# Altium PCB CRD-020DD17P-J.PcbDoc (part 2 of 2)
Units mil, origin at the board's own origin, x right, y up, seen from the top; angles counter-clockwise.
Board outline 2331 x 1574.8 mil, 4 copper layers (TOP, GND02, PWR03, BOTTOM), stack 63 mil thick; 83 components, 45 nets, 202 pads, 150 vias.
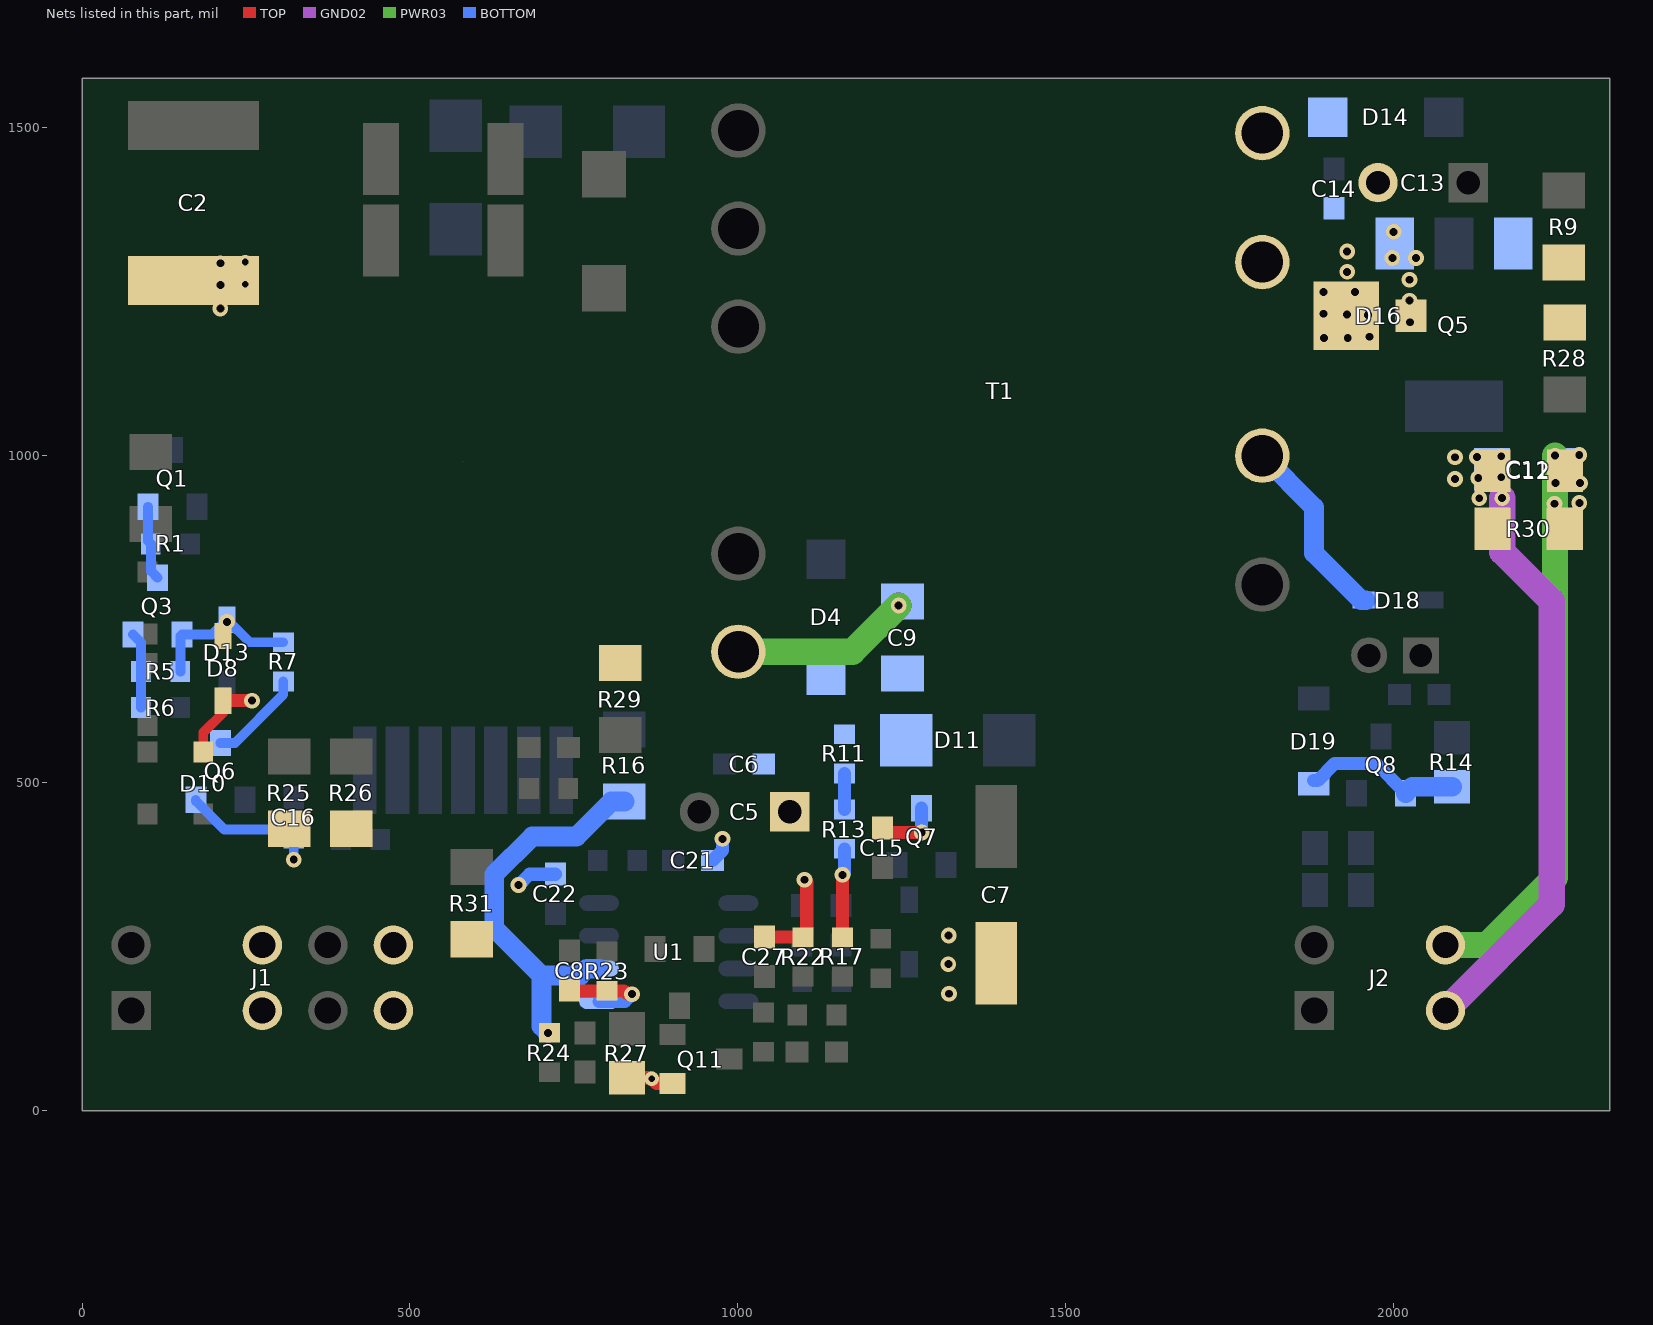
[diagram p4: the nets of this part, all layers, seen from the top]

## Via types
v1: diameter 24, hole 12, TOP to BOTTOM, 134 vias
v2: diameter 22, hole 10, TOP to BOTTOM, 16 vias

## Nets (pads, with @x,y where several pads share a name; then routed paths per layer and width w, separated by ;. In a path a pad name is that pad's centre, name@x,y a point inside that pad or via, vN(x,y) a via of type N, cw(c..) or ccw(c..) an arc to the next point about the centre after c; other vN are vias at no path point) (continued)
NETD8_2: D8.2 D13.1 Q3.B R5.2 R7.2 | length 260.1
  TOP w15: D8.2@215,724.02 215,739.8 v1(221,745.8)
  BOTTOM w15: R5.2@150,669.8 150,724.09 Q3.B@152.4,726.49 198.48,726.49 D13.1@221,749.02 255.21,714.8 R7.2@307,714.8
NETD14_1: D14.1 T1.14
NETD16_2: D16.2 Q5.1 R9.1 R28.1
  other v1: 2026,1202.8 2025,1235.8 2025,1267.8 1999,1300.8 2035,1300.8 2001,1340.8
NETD18_1: D18.1 T1.10 | length 290
  BOTTOM w30: T1.10@1800.61,999.38 1879.55,920.43 1879.55,850.62 1951.35,778.82 D18.1@1958.35,778.82
NETD19_2: D19.2 Q8.B R14.1 | length 244.5
  BOTTOM w20: D19.2@1879.15,503.7 1884.9,503.7 1911,529.8 1974.08,529.8 Q8.B@2019.39,484.49
  BOTTOM w30: Q8.B@2019.39,484.49 2029.2,494.3 R14.1@2090,494.3
NETQ1_E: Q1.E Q3.C R1.1 | length 114.3
  BOTTOM w15: Q1.E@100.6,921.49 100.6,869.21 R1.1@105,864.8 105,823.11 Q3.C@115,813.11
NETQ3_E: Q3.E R5.1 R6.2 | length 116.8
  BOTTOM w15: Q3.E@77.6,726.49 90,714.09 R5.1@90,669.8 R6.2@90,614.8
NETQ6_3: Q6.3 R7.1 | length 146.5
  BOTTOM w15: Q6.3@210.99,561.11 233.31,561.11 307,634.8 R7.1@307,654.8
NETR11_2: R11.2 R13.2 | length 55
  BOTTOM w20: R13.2@1163.08,459.43 R11.2@1163.08,514.43
NETR13_1: R13.1 R17.1 | length 135.9
  TOP w20: R17.1@1160,264.8 v1(1160,359.83)
  BOTTOM w20: v1(1160,359.83) 1163.08,362.91 R13.1@1163.08,399.43
NETR16_1: R16.1 R24.2 U1.6 | length 614.6
  TOP w20: v1(711.12,118.74) R24.2@713.12,118.74
  BOTTOM w30: v1(711.12,118.74) 700.95,128.91 700.95,206.36 ; U1.6@788.7,216.8 770.39,216.8 759.95,206.36 700.95,206.36 ; R16.1@827.49,471.7 807.49,471.7 754.24,418.45 686.95,418.45 628.71,360.21 628.71,278.6 700.95,206.36
P_15V: C5.1 C6.1 C9.1 D4.2 D11.1 J1.9 J1.10 R11.1 R31.2
PGND: C2.2 C7.2 C8.2 C9.2 C15.2 C16.1 C21.1 C22.1 C27.1 D8.1 D10.1 J1.5 J1.6 Q6.2 Q7.3 Q11.2 R22.1 R23.2 R25.2 R26.2 R27.2 R29.2 T1.6 U1.5 | length 1204.2
  TOP w15: D10.1@185,547.05 185,576.8 215,606.8 D8.1@215,625.59
  TOP w20: D8.1@215,625.59 v1(259.21,625.59) ; C8.2@744,183.8 745,182.8 R23.2@801,182.8 827,182.8 832,177.8 v1(839,177.8) ; R27.2@831.07,50.32 867.63,50.32 v2(869.03,48.92) 876.55,41.41 Q11.2@900.76,41.41 ; C27.1@1041,264.8 R22.1@1100,264.8 1105.55,270.35 1105.55,348.84 v1(1102.1,352.29) ; C15.2@1220.96,431.3 1227.77,424.49 v1(1280.97,424.49)
  PWR03 w40: T1.6@1001.39,700.17 1175.21,700.17 v1(1245.8,770.75)
  BOTTOM w5: v1(1245.8,770.75) C9.2@1251.74,776.69
  BOTTOM w15: Q6.2@173.58,474.49 173.58,472.22 217,428.8 312,428.8 C16.1@323,417.8 v1(323,383.02)
  BOTTOM w20: v1(666.02,344.19) 682.63,360.8 C22.1@722,360.8 ; U1.5@788.7,166.8 828,166.8 v1(839,177.8) ; C21.1@962,381.8 977.02,396.82 v1(977.02,414.8) ; v1(1280.97,424.49) Q7.3@1280.97,461.58
  other v1: 1322.52,178.44 1321.66,223.59 1322.09,267.45 211,1223.8 211,1259.8 211,1292.8
  other v2: 249,1260.8 249,1294.8
S_15V: C11.1 C12.1 J2.6 Q5.3 R30.2 | length 853.1
  PWR03 w40: J2.6@2080,252.8 2143.76,252.8 2247.12,356.16 v1(2247.12,999.36)
  other v1: 2246.28,925.97 2284.28,926.97 2248.12,957.36 2285.12,957.36 2284.12,1000.36
SGND: C11.2 C12.2 C13.2 C14.2 D16.1 J2.5 R30.1 T1.12 | length 880.3
  GND02 w40: J2.5@2080,152.8 2242.27,315.07 2242.27,777.14 2166.52,852.89 v1(2166.52,934.53)
  other v1: 2131.54,934.36 2094.55,963.82 2130.12,965.36 2165.12,966.36 2094.55,996.82 2128.12,997.36 2165.12,998.36 1895,1178.8 1931,1178.8 1964,1180.8 1962,1213.8 1930,1214.8 1894,1215.8 1894,1248.8 1942,1248.8 1930,1279.8 1930,1310.8
pads on no net: T1.2

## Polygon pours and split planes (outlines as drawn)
NETD4_1 on BOTTOM "BOTTOM-NETD4_1" (solid, remove dead copper, pour order 8): 976,889.8 1088,889.8 1106,871.8 1151,871.8 1161.64,871.8 1165.31,868.13 1165.31,858.11 1165,857.8 1165,817.8 1165,810.84 1161.27,807.11 1154.31,807.11 1154,806.8 988,806.8 972.49,806.8 959,820.29 959,835.8 959,872.8
P_15V on BOTTOM "BOTTOM-P_15V" (solid, remove dead copper, pour order 27): 1110,695.8 1102,687.8 1102,686.8 1092.47,677.27 1092.47,621.47 1040.88,569.88 1029.12,558.12 1029.12,429.39 1038.87,419.64 1050.96,419.64 1101.72,419.64 1117.85,435.77 1117.85,537.42 1136.68,556.25 1200.21,556.25 1209.28,547.18 1209.28,529.55 1218.02,520.81 1296.33,520.81 1300.03,524.51 1300.03,570.39 1300.03,683.16 1285.83,697.36 1111.56,697.36
NETC13_1 on BOTTOM "BOTTOM-NETC13_1" (solid, remove dead copper, pour order 25): 2121,1528.8 2146,1503.8 2146,1390.8 2123,1367.8 2123,1361.8 2123,1159.8 2168,1114.8 2168,1039.8 2164,1035.8 2023,1035.8 2018,1040.8 2018,1109.8 2064,1155.8 2064,1282.8 2064,1362.8 2080,1378.8 2080,1433.8 2046,1467.8 2046,1521.8 2046,1544.8 2048,1546.8 2103,1546.8
NETC1_1 on BOTTOM "BOTTOM-NETC1_1" (solid, remove dead copper, pour order 17): 818,1452.8 906,1452.8 971,1452.8 1002,1452.8 1022,1452.8 1043,1473.8 1043,1516.8 1008,1551.8 820,1551.8 810,1541.8 810,1460.8
NETC7_1 on BOTTOM "BOTTOM-NETC7_1" (solid, remove dead copper, pour order 16): 1388.71,369.92 1452.85,369.92 1463.91,380.98 1463.91,600.71 1455.06,609.56 1375.34,609.56 1371.96,606.18 1371.96,514.51 1371.96,386.67
SGND on BOTTOM "BOTTOM-SGND" (solid, remove dead copper, pour order 2): 2108.96,1015.1 2174.96,1015.1 2181.96,1008.1 2181.96,941.1 2181.96,924.1 2177.96,920.1 2100.44,920.1 2082.1,938.44 2082.1,1005.64 2091.56,1015.1
NETD14_1 on BOTTOM "BOTTOM-NETD14_1" (solid, remove dead copper, pour order 5): 1931,1526.8 1931,1487.8 1927,1483.8 1847,1483.8 1831,1467.8 1815,1451.8 1784,1451.8 1761,1474.8 1761,1515.8 1779,1533.8 1792,1546.8 1922,1546.8 1931,1537.8
NETD16_2 on BOTTOM "BOTTOM-NETD16_2" (solid, remove dead copper, pour order 4): 1974,1363.8 1974,1296.8 2004,1266.8 2004,1210.8 2004,1200.8 2010,1194.8 2016,1188.8 2044,1188.8 2050,1194.8 2056,1200.8 2056,1338.8 2034,1360.8 2031,1363.8
NETD2_2 on BOTTOM "BOTTOM-NETD2_2" (solid, remove dead copper, pour order 7): 606,1385.8 457,1385.8 441,1369.8 441,1317.8 456,1302.8 599,1302.8 610,1313.8 610,1381.8
S_15V on BOTTOM "BOTTOM-S_15V" (solid, remove dead copper, pour order 18): 2184,1048.31 2184,1270.8 2172,1282.8 2159,1282.8 2153,1288.8 2153,1351.8 2165,1363.8 2207,1363.8 2213,1363.8 2224,1352.8 2224,1104.63 2297.09,1031.54 2297.09,949.41 2290.64,942.96 2235.17,942.96 2226.14,951.99 2226.14,1006.17
NETD6_1 on BOTTOM "BOTTOM-NETD6_1" (solid, remove dead copper, pour order 30): 735,1129.8 425,1129.8 375,1129.8 370,1124.8 370,864.8 375,859.8 420,859.8 430,859.8 485,859.8 785,859.8 787.5,862.3 790,862.3 790,944.8 790,1054.8 794.5,1059.3 889,1153.8 999,1153.8 1028,1153.8 1042,1167.8 1042,1221.8 1024,1239.8 995,1239.8 952,1239.8 875,1239.8 765,1129.8
NETC24_1 on BOTTOM "BOTTOM-NETC24_1" (solid, remove dead copper, pour order 26): 645,449.8 415,449.8 410,454.8 410,470.8 410,502.8 394,518.8 289,518.8 283,524.8 283,586.8 291,594.8 420,594.8 643,594.8 649,588.8 649,453.8
NETD1_2 on BOTTOM "BOTTOM-NETD1_2" (solid, remove dead copper, pour order 10): 537,1544.8 721,1544.8 731,1534.8 731,1454.8 728,1451.8 626,1451.8 615,1462.8 535,1462.8 530,1467.8 530,1537.8
SGND on BOTTOM "BOTTOM-SGND 1" (solid, remove dead copper, pour order 21): 1775,1254.8 1761,1268.8 1761,1274.8 1761,1281.8 1761,1314.8 1782,1335.8 1840,1393.8 1936,1393.8 1938,1393.8 1947,1402.8 1947,1425.8 1966,1444.8 1995,1444.8 2008.5,1431.3 2008.5,1411.3 2008.5,1398.8 1997,1387.3 1968.5,1387.3 1956,1374.8 1956,1284.8 1956,1262.8 1978,1240.8 1978,1168.8 1970,1160.8 1885,1160.8 1872,1173.8 1872,1257.8 1905,1290.8 1905,1334.8 1900,1339.8 1887,1339.8 1886,1338.8 1879,1338.8 1845,1304.8 1845,1269.8 1830,1254.8
NETC1_1 on TOP "TOP-NETC1_1" (solid, remove dead copper, pour order 13): 60,1481.8 60,1537.8 77,1554.8 268,1554.8 281,1541.8 281,1474.8 272,1465.8 76,1465.8
PGND on TOP "TOP-PGND" (solid, remove dead copper, pour order 20): 280,364.8 280.5,364.3 245,328.8 245,129.8 258,116.8 287,116.8 310,139.8 310,257.8 311.01,258.81 311.01,304.51 351.18,344.68 394.54,388.04 435.87,388.04 442.81,394.98 442.81,457.78 440.62,459.97 284.96,459.97 282.61,457.62 282.61,367.41
NETC13_1 on TOP "TOP-NETC13_1" (solid, remove dead copper, pour order 9): 2289.61,1375.39 2091.31,1375.39 2081.9,1384.8 2081.9,1445.31 2086.6,1450.01 2282.89,1450.01 2294.32,1438.58 2294.32,1380.1
AGND on TOP "TOP-AGND" (solid, remove dead copper, pour order 29): 343.27,136.96 343.27,266.02 343.27,309 406.38,372.11 482.3,372.11 486.38,376.19 536.21,426.02 639.17,426.02 675.13,461.98 682.92,461.98 763.08,461.98 778.88,477.78 778.88,592.06 792.32,605.5 958.36,605.5 974.76,589.1 974.76,439.05 932.82,397.11 697.54,397.11 636.12,335.7 636.04,335.61 549.83,335.61 518.06,303.84 455.12,303.84 424.11,272.83 424.11,268.38 424.11,135.95 410.67,122.51 357.72,122.51
NETD2_2 on TOP "TOP-NETD2_2" (solid, remove dead copper, pour order 6): 436,1507.8 477,1507.8 483,1501.8 483,1280.8 475,1272.8 432,1272.8 428,1276.8 428,1499.8
NETC24_1 on TOP "TOP-NETC24_1" (solid, remove dead copper, pour order 23): 480.65,450.8 638,450.8 648,460.8 648,585.8 644,589.8 455,589.8 285,589.8 270,574.8 270,520.81 280.42,510.39 440.58,510.39 449.99,500.98 449.99,481.46
S_15V on TOP "TOP-S_15V" (solid, remove dead copper, pour order 3): 2231.95,1011.67 2287.95,1011.67 2294.95,1004.67 2294.95,910.67 2294.95,872.51 2294.95,857.41 2289.78,852.24 2234.96,852.24 2232.64,854.57 2232.64,865.39 2232.64,905.99 2231.95,906.67
NETC13_1 on TOP "TOP-NETC13_1 1" (solid, remove dead copper, pour order 15): 2161,1035.8 2075,1035.8 2059,1051.8 2059,1114.8 2064,1119.8 2065.83,1121.63 2295.66,1121.63 2298.69,1118.6 2298.69,1047.01 2287.3,1035.62 2170.82,1035.62 2161.18,1035.62
PGND on TOP "TOP-PGND 1" (solid, remove dead copper, pour order 11): 1047,718.8 1023,742.8 983,742.8 982,741.8 974,741.8 953,720.8 844,720.8 792.5,720.8 785.77,714.07 785.77,655.92 790.14,651.55 852.99,651.55 860.24,658.8 963,658.8 963.5,659.31 974,648.8 1022,648.8 1047,673.8
P_15V on TOP "TOP-P_15V" (solid, remove dead copper, pour order 28): 461.7,120.76 444.28,138.17 444.28,269.97 461.76,287.45 621.99,287.45 712.83,378.29 954.33,378.29 1038.36,462.32 1038.36,475.93 1053.9,491.47 1108.02,491.47 1117.43,482.06 1117.43,430.98 988.69,302.24 755.77,302.24 744.34,290.81 742.65,290.81 707.7,255.86 647.32,195.48 571.08,195.48 530.26,154.66 496.36,120.76
NETD16_2 on TOP "TOP-NETD16_2" (solid, remove dead copper, pour order 22): 2125.5,1241.3 2144,1259.8 2145,1259.8 2205,1319.8 2285,1319.8 2295,1309.8 2295,1189.8 2285,1179.8 2020.5,1179.8 2016,1179.8 2010,1185.8 2009,1185.8 2005.5,1189.3 2005.5,1271.3 1974,1302.8 1974,1359.8 1978,1363.8 2024,1363.8 2028,1363.8 2035.5,1356.31 2057,1334.8 2057,1263.8 2079.5,1241.3
NETD6_2 on TOP "TOP-NETD6_2" (solid, remove dead copper, pour order 19): 685,1509.8 620,1509.8 620,1269.8 670,1269.8 670,1369.8 670,1389.8 674,1393.8 821,1393.8 830,1402.8 830,1484.8 805,1509.8
NETD6_1 on TOP "TOP-NETD6_1" (solid, remove dead copper, pour order 32): 735,1129.8 425,1129.8 375,1129.8 370,1124.8 370,864.8 375,859.8 420,859.8 430,859.8 485,859.8 785,859.8 785,939.8 785,1058.8 881,1154.8 1010,1154.8 1041,1185.8 1041,1212.8 1018,1235.8 999,1235.8 884,1235.8 880,1239.8 865,1254.8 830,1289.8 767,1289.8 763,1285.8 763,1157.8 745,1139.8
PGND on TOP "TOP-PGND 2" (solid, remove dead copper, pour order 12): 66,1217.8 60,1223.8 60,1297.8 67,1304.8 270,1304.8 273,1301.8 273,1234.8 267,1228.8 232,1228.8 215,1211.8 72,1211.8
PGND on TOP "TOP-PGND 3" (solid, remove dead copper, pour order 14): 1430.02,290.24 1430.02,159.52 1418.84,148.34 1305.32,148.34 1287.26,166.4 1287.26,278.2 1301.88,292.82 1427.44,292.82
SGND on TOP "TOP-SGND" (solid, remove dead copper, pour order 24): 1960,1268.8 1963,1265.8 1970,1265.8 1978,1257.8 1978,1181.8 2045,1114.8 2045,1043.8 2045,1025.42 2053.49,1016.93 2101.47,1016.93 2174.1,1016.93 2179.7,1011.33 2179.7,921.89 2179.7,857.4 2175.4,853.1 2125.31,853.1 2105.96,872.45 2105.96,922.75 2075.43,953.28 2029.85,953.28 1995,988.13 1995,999.8 1995,1104.8 1938,1161.8 1882,1161.8 1877,1166.8 1877,1263.8 1877,1287.8 1916,1326.8 1945,1326.8 1956,1315.8 1956,1272.8
NETD6_1 on GND02 "GND02-NETD6_1" (solid, remove dead copper, pour order 31): 846,1236.8 739,1129.8 375,1129.8 375,864.8 379,860.8 789,860.8 791,862.8 791,944.8 792.5,946.3 792.5,1058.3 888,1153.8 894.5,1160.3 1030.5,1160.3 1045,1174.8 1045,1216.8 1025,1236.8
NETC1_1 on GND02 "GND02-NETC1_1" (solid, remove dead copper, pour order 34): 116,124.8 110,124.8 55,124.8 45,134.8 45,1497.8 92,1544.8 150,1544.8 215,1544.8 930,1544.8 1031,1544.8 1052,1523.8 1052,1482.8 1025,1455.8 824,1455.8 800,1479.8 465,1479.8 245,1479.8 180,1479.8 150,1449.8 150,1384.8 150,1094.8 150,1004.8 150,427.8 139,416.8 139,260.8 139,147.8
SGND on GND02 "GND02-SGND" (solid, remove dead copper, pour order 1): 2085.4,1012.53 2174.4,1012.53 2181.4,1005.53 2181.4,928.53 2175.4,922.53 2113.4,922.53 2080.4,955.53 2080.4,1007.53
NETD6_1 on PWR03 "PWR03-NETD6_1" (solid, remove dead copper, pour order 33): 881,1240.8 774,1133.8 374,1133.8 362,1121.8 362,876.8 378,860.8 784,860.8 791,867.8 791,944.8 791,988.8 791,1020.8 861,1090.8 918,1147.8 1036,1147.8 1050,1161.8 1050,1225.8 1026,1249.8 890,1249.8
S_15V on PWR03 "PWR03-S_15V" (solid, remove dead copper, pour order 0): 2240.52,906.68 2234.52,912.68 2234.52,1011.68 2237.52,1014.68 2290.52,1014.68 2298.52,1006.68 2298.52,914.68 2290.52,906.68
PGND on PWR03 "PWR03-PGND" (solid, remove dead copper, pour order 35): 302,734.8 302,511.8 346.5,467.3 346.5,319.3 347,318.8 347,303.8 319,275.8 319,147.8 358,108.8 416,108.8 427,108.8 429,110.8 505,110.8 569,174.8 569,299.8 568.5,300.3 568.5,343.3 659,433.8 659,594.8 701,636.8 879,636.8 977,734.8 1030,734.8 1040,724.8 1040,650.8 1056,634.8 1466.58,634.8 1498.58,602.8 1498.58,193.85 1326.53,21.8 586,21.8 308,21.8 253,76.8 232,97.8 232,146.8 232,367.8 66,533.8 66,1295.8 77,1306.8 268,1306.8 300,1274.8 300,734.8

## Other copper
TOP:
  text "TOP" at 910,-190 h60
GND02:
  text "GND02" at 910,-190 h60
PWR03:
  text "PWR03" at 910,-190 h60
BOTTOM:
  text "BOTTOM" at 910,-190 h60

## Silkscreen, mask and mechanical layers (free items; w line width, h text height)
Top Overlay:
  drawing of 6236 lines, arcs and shapes, not listed
  text "CRD-020DD17P-J rev 1.0" at 72.24,1150.23 h35
  text "Silkscreen TOP" at 910,-190 h60
Bottom Overlay:
  text "Silkscreen BOTTOM" at 910,-190 h60
  text "SILKSCREEN BOTTOM" at 9573,-250 h100
Top Paste:
  text "Paste TOP" at 910,-190 h60
Bottom Paste:
  text "Paste BOTTOM" at 910,-190 h60
Top Solder:
  region: 375,1129.8 775,1129.8 785,1119.8 785,859.8 375,859.8 370,864.8 370,1124.8
  text "Soldermask TOP" at 910,-190 h60
  text "SOLDERMASK TOP" at 8333,-250 h100
Bottom Solder:
  region: 375,1129.8 778,1129.8 788,1119.8 788,862.8 785,859.8 375,859.8 370,864.8 370,1124.8
  text "Soldermask BOTTOM" at 910,-190 h60
  text "SOLDERMASK BOTTOM" at 9573,-250 h100
DESIGN_OUTLINE:
  lines w1: 0,0 2331,0 2331,1574.8 0,1574.8 0,0
DIMENSION:
  drawing of 890 lines, arcs and shapes, not listed
  text "40" at -1513.5,733.3 h125
  text "40" at -1513.5,733.3 h125
  text "1574.80" at -1046.5,733.3 h125
  text "1574.80" at -1046.5,733.3 h125
  text "59.21" at 324.5,-377.7 h125
  text "59.21" at 324.5,-377.7 h125
  text "2331.00" at 1163.5,-377.7 h125
  text "2331.00" at 1163.5,-377.7 h125
Title Block:
  lines w7.9: -11414.06,-7979.09 12601.64,-7979.09 ; -11414.06,-7979.09 12601.64,-7979.09 ; -11414.06,-7979.09 -11414.06,9343.71 ; -11414.06,-7979.09 -11414.06,9343.71 ; -11414.06,9343.71 12601.64,9343.71 ; -11414.06,9343.71 12601.64,9343.71 ; 12601.64,-7979.09 12601.64,9343.71 ; 12601.64,-7979.09 12601.64,9343.71
  lines w8: -10626.67,-7191.68 -10626.67,8556.32 ; -10626.67,-7191.68 -10626.67,8556.32 ; -10626.67,-7191.68 11814.24,-7191.68 ; -10626.67,-7191.68 11814.24,-7191.68 ; -10626.67,8556.32 11814.24,8556.32 ; -10626.67,8556.32 11814.24,8556.32 ; 7411.83,8006.32 11811.83,8006.32 7411.83,8006.32 ; 7411.83,8006.32 7411.83,8056.32 ; 7411.83,8006.32 7411.83,8056.32 ; 7411.83,8056.32 7411.83,8556.32 7411.83,8056.32 ; 7861.83,8156.32 7861.83,8306.32 7861.83,8156.32 ; 7861.83,8156.32 7861.83,8006.32 7861.83,8156.32 ; 9911.83,8156.32 9911.83,8306.32 9911.83,8156.32 ; 9911.83,8156.32 9911.83,8006.32 9911.83,8156.32 ; 10461.83,8156.32 10461.83,8306.32 10461.83,8156.32 ; 10461.83,8156.32 10461.83,8006.32 10461.83,8156.32 ; 11036.83,8156.32 11036.83,8306.32 11036.83,8156.32 ; 11036.83,8156.32 11036.83,8006.32 11036.83,8156.32 ; 11814.24,-7191.68 11814.24,8556.32 ; 11814.24,-7191.68 11814.24,8556.32 ; -11413.76,-5156.29 -10628.06,-5156.29 -11413.76,-5156.29 ; -11413.76,-1156.29 -10628.06,-1156.29 -11413.76,-1156.29 ; -11413.76,2843.71 -10628.06,2843.71 -11413.76,2843.71 ; -11413.76,6843.71 -10628.06,6843.71 -11413.76,6843.71 ; -11412.67,9341.51 -10626.06,8554.82 -11412.67,9341.51 ; -11412.46,-7977.09 -10625.67,-7190.29 -11412.46,-7977.09 ; -7414.06,-7978.79 -7414.06,-7193.39 -7414.06,-7978.79 ; -7414.06,8556.71 -7414.06,9342.01 -7414.06,8556.71 ; -3414.06,-7978.79 -3414.06,-7193.39 -3414.06,-7978.79 ; -3414.06,8556.71 -3414.06,9342.01 -3414.06,8556.71 ; 585.94,-7978.79 585.94,-7193.39 585.94,-7978.79 ; 585.94,8556.71 585.94,9342.01 585.94,8556.71 ; 4585.94,-7978.79 4585.94,-7193.39 4585.94,-7978.79 ; 4585.94,8556.71 4585.94,9342.01 4585.94,8556.71 ; 7411.83,8152.32 11809.83,8152.32 7411.83,8152.32 ; 7411.83,8306.32 11811.83,8306.32 7411.83,8306.32 ; 8585.94,-7978.79 8585.94,-7193.39 8585.94,-7978.79 ; 8585.94,8556.71 8585.94,9342.01 8585.94,8556.71 ; 11813.44,-7190.09 12599.74,-7976.29 11813.44,-7190.09 ; 11813.74,8554.82 12600.94,9342.01 11813.74,8554.82 ; 11814.54,-5156.29 12600.24,-5156.29 11814.54,-5156.29 ; 11814.54,-1156.29 12600.24,-1156.29 11814.54,-1156.29 ; 11814.54,2843.71 12600.24,2843.71 11814.54,2843.71 ; 11814.54,6843.71 12600.24,6843.71 11814.54,6843.71
  text "2" at -5414.67,8844.11 h250
  text "2" at -5414.67,8844.11 h250
  text "6" at 10539.33,8836.41 h250
  text "6" at 10539.33,8836.41 h250
  text "1" at -9129.56,8828.71 h250
  text "1" at -9129.56,8828.71 h250
  text "3" at -1514.76,8820.91 h250
  text "3" at -1514.76,8820.91 h250
  text "5" at 6577.83,8821.01 h250
  text "5" at 6577.83,8821.01 h250
  text "4" at 2446.74,8805.51 h250
  text "4" at 2446.74,8805.51 h250
  text "REVISIONS" at 9106.44,8359.61 h80
  text "REVISIONS" at 9106.44,8359.61 h80
  text "REV" at 7577.24,8205.41 h35
  text "REV" at 7577.24,8205.41 h35
  text "DESCRIPTION" at 8652.24,8205.41 h35
  text "DESCRIPTION" at 8652.24,8205.41 h35
  text "APPROVAL" at 10627.24,8205.41 h35
  text "APPROVAL" at 10627.24,8205.41 h35
  text "DATE" at 11327.24,8205.41 h35
  text "DATE" at 11327.24,8205.41 h35
  text "CHECK" at 10082.24,8200.41 h35
  text "CHECK" at 10082.24,8200.41 h35
  text "1.0" at 7586.64,8060.91 h35
  text "A" at -11117.96,7826.82 h250
  text "A" at -11117.96,7826.82 h250
  text "A" at 12110.33,7826.82 h250
  text "A" at 12110.33,7826.82 h250
  text "B" at -11102.56,4774.71 h250
  text "B" at -11102.56,4774.71 h250
  text "B" at 12125.74,4774.71 h250
  text "B" at 12125.74,4774.71 h250
  text "C" at -11148.86,751.51 h250
  text "C" at -11148.86,751.51 h250
  text "C" at 12079.54,751.51 h250
  text "C" at 12079.54,751.51 h250
  text "D" at -11133.46,-3225.39 h250
  text "D" at -11133.46,-3225.39 h250
  text "D" at 12094.94,-3225.39 h250
  text "D" at 12094.94,-3225.39 h250
  text "E" at -11133.46,-6508.79 h250
  text "E" at -11133.46,-6508.79 h250
  text "E" at 12094.94,-6508.79 h250
  text "E" at 12094.94,-6508.79 h250
  text "2" at -5414.67,-7691.39 h250
  text "2" at -5414.67,-7691.39 h250
  text "6" at 10539.33,-7699.09 h250
  text "6" at 10539.33,-7699.09 h250
  text "1" at -9129.56,-7706.79 h250
  text "1" at -9129.56,-7706.79 h250
  text "3" at -1514.76,-7714.49 h250
  text "3" at -1514.76,-7714.49 h250
  text "5" at 6577.83,-7714.49 h250
  text "5" at 6577.83,-7714.49 h250
  text "4" at 2446.74,-7729.89 h250
  text "4" at 2446.74,-7729.89 h250
Fab Notes:
  drawing of 241 lines, arcs and shapes, not listed
  text "REFERENCE LAYER STACKUP" at 7231,2201.8 h100
  text "(Unit:mils)" at 9081,2201.8 h63
  text "Layer1" at 9156,1901.8 h63
  text "TOP" at 9581,1901.8 h63
  text "1.40 mil" at 10006,1901.8 h63
  text "Copper+Plating" at 10606,1901.8 h63
  text "Prepreg" at 6733.2,1831.8 h63
  text "8.50 mil" at 6356,1826.8 h63
  text "Layer2" at 9156,1751.8 h63
  text "GND02" at 9581,1751.8 h63
  text "1.20 mil" at 10006,1751.8 h63
  text "1.60mm" at 5956,1681.8 h63
  text "Core" at 6884.4,1681.8 h63
  text "40.80 mil" at 6356,1676.8 h63
  text "Layer3" at 9156,1601.8 h63
  text "PWR03" at 9581,1601.8 h63
  text "1.20 mil" at 10006,1601.8 h63
  text "Prepreg" at 6733.2,1531.8 h63
  text "8.50 mil" at 6356,1526.8 h63
  text "Layer4" at 9156,1451.8 h63
  text "BOTTOM" at 9581,1451.8 h63
  text "1.40 mil" at 10006,1451.8 h63
  text "Copper+Plating" at 10606,1451.8 h63
  text "Purchase Order & Specification Sheet" at 6939.64,247.91 h80
  text "Board Name :" at 6239.64,47.91 h35
  text "Board Thickness :" at 7839.64,47.91 h35
  text "1.60mm +/- 10%" at 8449.64,47.91 h35
  text "Layers :" at 9039.64,47.91 h35
  text "4" at 9589.64,47.91 h35
  text "Dielectric Material :" at 6239.64,-102.09 h35
  text "FR4" at 6989.64,-102.09 h35
  text "Spell   Mode  :" at 7839.64,-102.09 h35
  text "2X 5" at 8449.64,-102.09 h35
  text "Board Cut Out :" at 9039.64,-102.09 h35
  text "No" at 9589.64,-102.09 h35
  text "Surface  Finished :" at 6239.64,-302.09 h35
  text "Immersion Gold" at 7189.64,-302.09 h35
  text "Gold Thickness:" at 9039.64,-302.09 h35
  text ">=0.05um" at 9589.64,-302.09 h35
  text "Soldermask Colors :" at 6239.64,-452.09 h35
  text "Green" at 7189.64,-452.09 h35
  text "E-TEST Checker :" at 7839.64,-452.09 h35
  text "Yes" at 8449.64,-452.09 h35
  text "Silk Screen Colors :" at 6239.64,-602.09 h35
  text "White" at 7189.64,-602.09 h35
  text "UL-MAKE :" at 7839.64,-602.09 h35
  text "Yes" at 8449.64,-602.09 h35
  text "UL-MAKE Layer :" at 9039.64,-602.09 h35
  text "Silk Top" at 9589.64,-602.09 h35
  text "Outline Profile :" at 6239.64,-752.09 h35
  text "Router" at 7189.64,-752.09 h35
  text "Gold Finger Plating:" at 7839.64,-752.09 h35
  text "No" at 8449.64,-752.09 h35
  text "Fab Notes:" at 6189.64,-902.09 h35
  text "1. Fabricate to IPC-6012-II, current revision." at 6189.64,-1002.09 h35
  text "2. All vias need to be plugged." at 6189.64,-1102.09 h35
  text "3. Attention: the thickness of the material's adjustment should be less than 20% for each layer(Core/PP)." at 6189.64,-1202.09 h35
  text "For instance: the thickness of Core-1 is 4mil, then the adjustment range will be 3.2-4.8mil." at 6189.64,-1302.09 h35
ASSEMBLY_BOTTOM:
  text "SECONDARY SIDE" at 9453,-250 h100
Drill Drawing:
  lines w1: -1077,-4550.2 3759,-4550.2 ; -1077,-4300.2 3759,-4300.2 ; -1077,-4050.2 3759,-4050.2 ; -1077,-3800.2 3759,-3800.2 ; -1077,-3550.2 3759,-3550.2 ; -1077,-3300.2 3759,-3300.2 ; -1077,-3050.2 3759,-3050.2 ; -1077,-2800.2 3759,-2800.2 ; -1077,-2550.2 3759,-2550.2 ; -667.5,-4675.2 -587.5,-4675.2 ; -667.5,-3675.2 -587.5,-3675.2 ; -649.5,-4425.2 -605.5,-4425.2 ; -647.5,-4175.2 -607.5,-4175.2 ; -647.5,-3925.2 -607.5,-3925.2 ; -647.5,-3425.2 -607.5,-3425.2 ; -647.5,-3175.2 -607.5,-3175.2 ; -627.5,-4715.2 -627.5,-4635.2 ; -627.5,-4447.2 -627.5,-4403.2 ; -627.5,-4195.2 -627.5,-4155.2 ; -627.5,-3945.2 -627.5,-3905.2 ; -627.5,-3715.2 -627.5,-3635.2 ; -627.5,-3445.2 -627.5,-3405.2 ; -627.5,-3195.2 -627.5,-3155.2 ; -178,-4800.2 -178,-2800.2 ; 1713,-4800.2 1713,-2800.2 ; 2984,-4800.2 2984,-2800.2 ; -1077,-4800.2 -1077,-2300.2 3759,-2300.2 3759,-4800.2 -1077,-4800.2
  text "DRILL CHART: TOP to BOTTOM" at 41,-2487.7 h125
  text "ALL UNITS ARE IN MILS" at 291,-2737.7 h125
  text "FIGURE" at -927.5,-2987.7 h125
  text "SIZE" at 567.5,-2987.7 h125
  text "PLATED" at 2048.5,-2987.7 h125
  text "QTY" at 3221.5,-2987.7 h125
  text "10.0" at 567.5,-3237.7 h125
  text "PLATED" at 2048.5,-3237.7 h125
  text "16" at 3271.5,-3237.7 h125
  text "12.0" at 567.5,-3487.7 h125
  text "PLATED" at 2048.5,-3487.7 h125
  text "134" at 3221.5,-3487.7 h125
  text "35.0" at 567.5,-3737.7 h125
  text "PLATED" at 2048.5,-3737.7 h125
  text "2" at 3321.5,-3737.7 h125
  text "36.0" at 567.5,-3987.7 h125
  text "PLATED" at 2048.5,-3987.7 h125
  text "4" at 3321.5,-3987.7 h125
  text "40.0" at 567.5,-4237.7 h125
  text "PLATED" at 2048.5,-4237.7 h125
  text "2" at 3321.5,-4237.7 h125
  text "40.0" at 567.5,-4487.7 h125
  text "PLATED" at 2048.5,-4487.7 h125
  text "10" at 3271.5,-4487.7 h125
  text "63.0" at 567.5,-4737.7 h125
  text "PLATED" at 2048.5,-4737.7 h125
  text "9" at 3321.5,-4737.7 h125
ASSEMBLY_TOP:
  text "PRIMARY SIDE" at 8413,-250 h100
